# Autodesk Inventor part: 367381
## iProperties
Created: 2006-07
Part Number: 367381
Material: A2
Description: Zylinderschraube
Vendor: Autodesk Inc.
Document SubType Name: Modeling
Standard: DIN 912
Designer: I.Baliuc
Standards Organization: DIN
Language: de-DE
Size Designation: M6 x 20
Categories: <MemberInstance Version="R10.0.0"><Categories><Category DisplayName="Schrauben" InternalName="e4da775c-781d-43d5-af7c-5136215cf5a6" Mnemonic="FSTN"><Category Di
Density: 8.08 g/cm^3
Abmessung: M6 x 20
Author: T.Messerschmitt
Comments: DIN 912 - M6 x 20
Revision Number: 367381
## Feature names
1. Körper [Revolution]
2. Loch [Extrusion]
3. Rundung1 [Fillet]
4. Fase1 [Chamfer]
